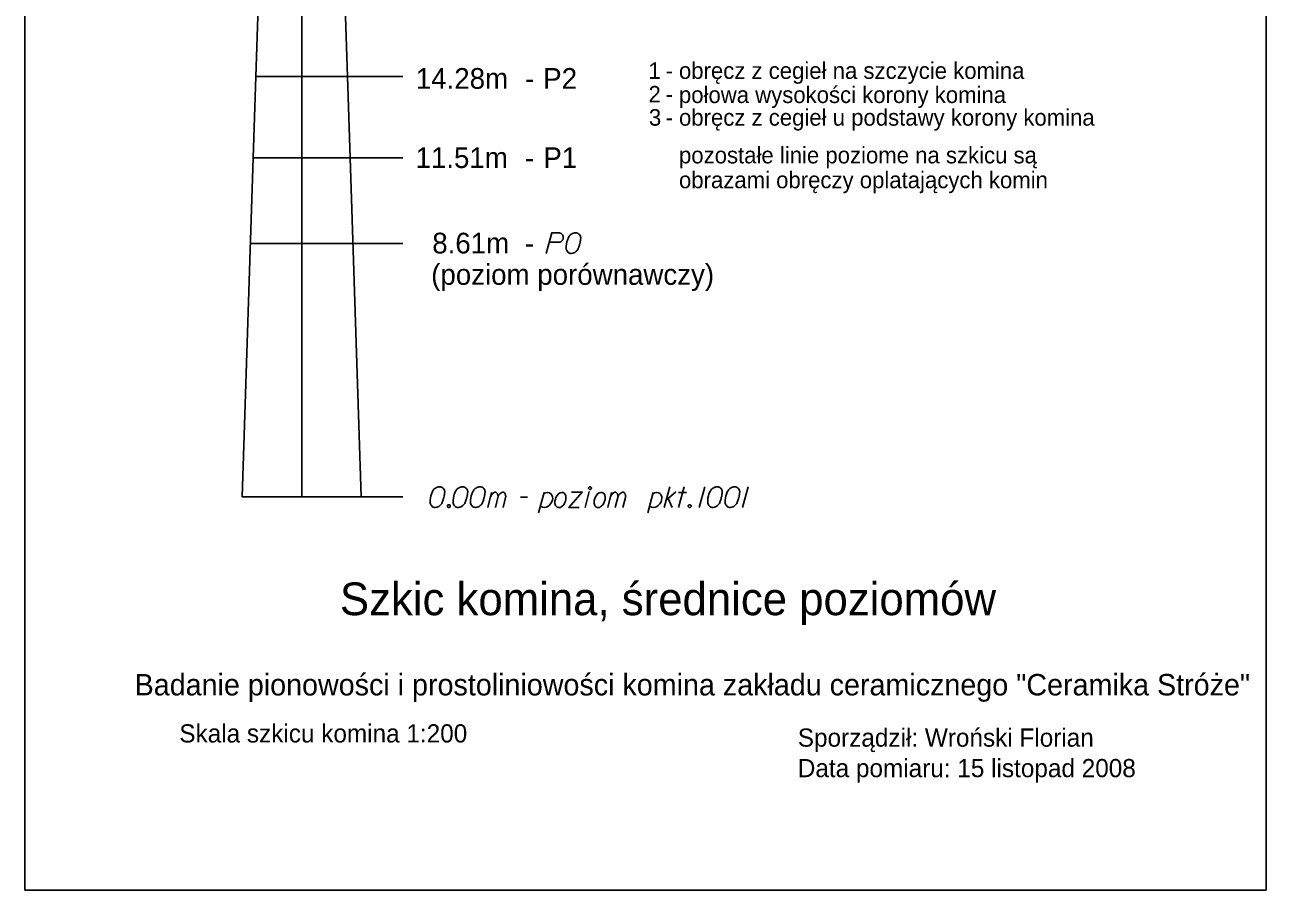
# Model space of a CAD drawing. Extents: x 138 to 6653, y -177 to 1520.
# Drawn here: x 316.78 to 337.78, y -30.54 to -15.91 of the extents above; entities that cross this region are included whole.
import ezdxf

# ---------------------------------------------------------------- set-up
doc = ezdxf.new("R2010")
doc.units = 0
for name, color, linetype in [('Opisy', 7, 'Continuous'), ('Ramka do drukowania', 7, 'Continuous'), ('Standard', 7, 'Continuous')]:
    doc.layers.add(name, color=color, linetype=linetype)

msp = doc.modelspace()

# ---------------------------------------------------------------- linework, layer by layer
at = {"layer": 'Ramka do drukowania'}
for p, q in [((316.779, -30.544), (316.779, -0.844)), ((337.779, -30.544), (337.779, -0.844)), ((316.779, -30.544), (337.779, -30.544))]:
    msp.add_line(p, q, dxfattribs=at)
at = {"layer": 'Standard'}
for p, q in [((321.463, -23.89), (321.463, -3.806)), ((320.689, -16.784), (320.731, -15.416)), ((322.237, -16.784), (322.195, -15.416)), ((320.644, -18.159), (320.689, -16.784)), ((321.463, -16.784), (320.689, -16.784)), ((321.463, -16.784), (323.173, -16.784)), ((322.282, -18.159), (322.237, -16.784)), ((320.457, -23.89), (320.644, -18.159)), ((321.463, -18.159), (320.644, -18.159)), ((321.463, -18.159), (323.173, -18.159)), ((322.469, -23.89), (322.282, -18.159)), ((321.463, -19.605), (320.597, -19.605)), ((321.463, -19.605), (323.173, -19.605)), ((321.463, -23.89), (320.457, -23.89)), ((321.463, -23.89), (323.173, -23.89))]:
    msp.add_line(p, q, dxfattribs=at)
for points in [[(325.6, -19.774), (325.694, -19.424), (325.812, -19.424), (325.829, -19.427), (325.837, -19.43), (325.854, -19.438), (325.865, -19.446), (325.873, -19.457), (325.881, -19.471), (325.887, -19.49), (325.889, -19.507), (325.887, -19.521), (325.884, -19.532), (325.878, -19.543), (325.873, -19.551), (325.865, -19.562), (325.854, -19.57), (325.845, -19.576), (325.832, -19.581), (325.818, -19.584), (325.652, -19.584)], [(326.102, -19.424), (326.096, -19.424), (326.08, -19.427), (326.069, -19.43), (326.06, -19.433), (326.047, -19.438), (326.03, -19.446), (326.016, -19.455), (326.002, -19.466), (325.994, -19.477), (325.986, -19.49), (325.978, -19.504), (325.969, -19.521), (325.964, -19.532), (325.958, -19.548), (325.95, -19.576), (325.942, -19.617), (325.936, -19.65), (325.936, -19.681), (325.939, -19.703), (325.95, -19.727), (325.958, -19.741), (325.972, -19.758), (325.989, -19.769), (325.997, -19.772), (326.013, -19.774), (326.027, -19.774), (326.049, -19.772), (326.069, -19.766), (326.082, -19.758), (326.102, -19.744), (326.11, -19.736), (326.121, -19.725), (326.129, -19.714), (326.135, -19.705), (326.14, -19.692), (326.143, -19.686), (326.149, -19.672), (326.154, -19.656), (326.16, -19.639), (326.162, -19.628), (326.165, -19.62), (326.168, -19.609), (326.173, -19.584), (326.176, -19.57), (326.179, -19.557), (326.182, -19.537), (326.184, -19.513), (326.184, -19.504), (326.182, -19.493), (326.179, -19.482), (326.171, -19.466), (326.162, -19.455), (326.154, -19.446), (326.143, -19.438), (326.132, -19.433), (326.124, -19.43), (326.115, -19.427), (326.102, -19.424)], [(323.8, -23.721), (323.794, -23.721), (323.778, -23.724), (323.767, -23.726), (323.759, -23.729), (323.745, -23.735), (323.728, -23.743), (323.714, -23.751), (323.701, -23.762), (323.692, -23.773), (323.684, -23.787), (323.676, -23.801), (323.668, -23.817), (323.662, -23.828), (323.657, -23.845), (323.648, -23.872), (323.64, -23.914), (323.635, -23.947), (323.635, -23.977), (323.637, -23.999), (323.648, -24.024), (323.657, -24.038), (323.67, -24.054), (323.687, -24.065), (323.695, -24.068), (323.712, -24.071), (323.725, -24.071), (323.748, -24.068), (323.767, -24.062), (323.781, -24.054), (323.8, -24.04), (323.808, -24.032), (323.819, -24.021), (323.827, -24.01), (323.833, -24.002), (323.838, -23.988), (323.841, -23.983), (323.847, -23.969), (323.852, -23.952), (323.858, -23.936), (323.861, -23.925), (323.863, -23.916), (323.866, -23.905), (323.872, -23.881), (323.874, -23.867), (323.877, -23.853), (323.88, -23.834), (323.883, -23.809), (323.883, -23.801), (323.88, -23.79), (323.877, -23.779), (323.869, -23.762), (323.861, -23.751), (323.852, -23.743), (323.841, -23.735), (323.83, -23.729), (323.822, -23.726), (323.814, -23.724), (323.8, -23.721)], [(324.188, -23.721), (324.183, -23.721), (324.166, -23.724), (324.155, -23.726), (324.147, -23.729), (324.133, -23.735), (324.117, -23.743), (324.103, -23.751), (324.089, -23.762), (324.081, -23.773), (324.073, -23.787), (324.064, -23.801), (324.056, -23.817), (324.051, -23.828), (324.045, -23.845), (324.037, -23.872), (324.029, -23.914), (324.023, -23.947), (324.023, -23.977), (324.026, -23.999), (324.037, -24.024), (324.045, -24.038), (324.059, -24.054), (324.075, -24.065), (324.084, -24.068), (324.1, -24.071), (324.114, -24.071), (324.136, -24.068), (324.155, -24.062), (324.169, -24.054), (324.188, -24.04), (324.197, -24.032), (324.208, -24.021), (324.216, -24.01), (324.221, -24.002), (324.227, -23.988), (324.23, -23.983), (324.235, -23.969), (324.241, -23.952), (324.246, -23.936), (324.249, -23.925), (324.252, -23.916), (324.255, -23.905), (324.26, -23.881), (324.263, -23.867), (324.266, -23.853), (324.268, -23.834), (324.271, -23.809), (324.271, -23.801), (324.268, -23.79), (324.266, -23.779), (324.257, -23.762), (324.249, -23.751), (324.241, -23.743), (324.23, -23.735), (324.219, -23.729), (324.21, -23.726), (324.202, -23.724), (324.188, -23.721)], [(324.483, -23.721), (324.478, -23.721), (324.461, -23.724), (324.45, -23.726), (324.442, -23.729), (324.428, -23.735), (324.412, -23.743), (324.398, -23.751), (324.384, -23.762), (324.376, -23.773), (324.368, -23.787), (324.359, -23.801), (324.351, -23.817), (324.345, -23.828), (324.34, -23.845), (324.332, -23.872), (324.323, -23.914), (324.318, -23.947), (324.318, -23.977), (324.321, -23.999), (324.332, -24.024), (324.34, -24.038), (324.354, -24.054), (324.37, -24.065), (324.379, -24.068), (324.395, -24.071), (324.409, -24.071), (324.431, -24.068), (324.45, -24.062), (324.464, -24.054), (324.483, -24.04), (324.492, -24.032), (324.503, -24.021), (324.511, -24.01), (324.516, -24.002), (324.522, -23.988), (324.525, -23.983), (324.53, -23.969), (324.536, -23.952), (324.541, -23.936), (324.544, -23.925), (324.547, -23.916), (324.549, -23.905), (324.555, -23.881), (324.558, -23.867), (324.56, -23.853), (324.563, -23.834), (324.566, -23.809), (324.566, -23.801), (324.563, -23.79), (324.56, -23.779), (324.552, -23.762), (324.544, -23.751), (324.536, -23.743), (324.525, -23.735), (324.514, -23.729), (324.505, -23.726), (324.497, -23.724), (324.483, -23.721)], [(326.333, -23.721), (326.346, -23.721), (326.355, -23.726), (326.363, -23.737), (326.363, -23.751), (326.355, -23.762), (326.346, -23.768), (326.333, -23.768), (326.324, -23.762), (326.316, -23.751), (326.316, -23.737), (326.324, -23.726), (326.333, -23.721)], [(327.595, -24.071), (327.689, -23.721)], [(327.84, -24.071), (327.931, -23.721)], [(328.284, -23.721), (328.19, -24.071)], [(328.496, -23.721), (328.49, -23.721), (328.474, -23.724), (328.463, -23.726), (328.455, -23.729), (328.441, -23.735), (328.424, -23.743), (328.411, -23.751), (328.397, -23.762), (328.388, -23.773), (328.38, -23.787), (328.372, -23.801), (328.364, -23.817), (328.358, -23.828), (328.353, -23.845), (328.344, -23.872), (328.336, -23.914), (328.331, -23.947), (328.331, -23.977), (328.333, -23.999), (328.344, -24.024), (328.353, -24.038), (328.366, -24.054), (328.383, -24.065), (328.391, -24.068), (328.408, -24.071), (328.422, -24.071), (328.444, -24.068), (328.463, -24.062), (328.477, -24.054), (328.496, -24.04), (328.504, -24.032), (328.515, -24.021), (328.523, -24.01), (328.529, -24.002), (328.535, -23.988), (328.537, -23.983), (328.543, -23.969), (328.548, -23.952), (328.554, -23.936), (328.557, -23.925), (328.559, -23.916), (328.562, -23.905), (328.568, -23.881), (328.57, -23.867), (328.573, -23.853), (328.576, -23.834), (328.579, -23.809), (328.579, -23.801), (328.576, -23.79), (328.573, -23.779), (328.565, -23.762), (328.557, -23.751), (328.548, -23.743), (328.537, -23.735), (328.526, -23.729), (328.518, -23.726), (328.51, -23.724), (328.496, -23.721)], [(328.791, -23.721), (328.785, -23.721), (328.769, -23.724), (328.758, -23.726), (328.749, -23.729), (328.736, -23.735), (328.719, -23.743), (328.705, -23.751), (328.692, -23.762), (328.683, -23.773), (328.675, -23.787), (328.667, -23.801), (328.658, -23.817), (328.653, -23.828), (328.647, -23.845), (328.639, -23.872), (328.631, -23.914), (328.625, -23.947), (328.625, -23.977), (328.628, -23.999), (328.639, -24.024), (328.647, -24.038), (328.661, -24.054), (328.678, -24.065), (328.686, -24.068), (328.703, -24.071), (328.716, -24.071), (328.738, -24.068), (328.758, -24.062), (328.772, -24.054), (328.791, -24.04), (328.799, -24.032), (328.81, -24.021), (328.818, -24.01), (328.824, -24.002), (328.829, -23.988), (328.832, -23.983), (328.838, -23.969), (328.843, -23.952), (328.849, -23.936), (328.851, -23.925), (328.854, -23.916), (328.857, -23.905), (328.862, -23.881), (328.865, -23.867), (328.868, -23.853), (328.871, -23.834), (328.873, -23.809), (328.873, -23.801), (328.871, -23.79), (328.868, -23.779), (328.86, -23.762), (328.851, -23.751), (328.843, -23.743), (328.832, -23.735), (328.821, -23.729), (328.813, -23.726), (328.805, -23.724), (328.791, -23.721)], [(329.014, -23.721), (328.92, -24.071)], [(324.613, -24.071), (324.676, -23.82)], [(324.66, -23.886), (324.673, -23.856), (324.687, -23.839), (324.704, -23.828), (324.72, -23.82), (324.731, -23.814), (324.748, -23.814), (324.753, -23.817), (324.764, -23.828), (324.775, -23.842), (324.784, -23.867), (324.786, -23.881), (324.8, -23.856), (324.817, -23.839), (324.833, -23.828), (324.85, -23.82), (324.864, -23.814), (324.877, -23.814), (324.888, -23.817), (324.897, -23.828), (324.905, -23.842), (324.913, -23.867), (324.916, -23.881), (324.869, -24.071)], [(324.74, -24.071), (324.786, -23.881)], [(325.164, -23.894), (325.283, -23.894)], [(325.47, -24.162), (325.564, -23.817)], [(325.556, -23.847), (325.583, -23.825), (325.624, -23.817), (325.658, -23.823), (325.68, -23.839), (325.696, -23.861), (325.707, -23.892), (325.71, -23.919), (325.704, -23.944), (325.696, -23.974), (325.674, -24.007), (325.647, -24.038), (325.605, -24.065), (325.569, -24.071), (325.536, -24.068), (325.5, -24.049)], [(325.864, -23.817), (325.884, -23.817), (325.906, -23.828), (325.928, -23.859), (325.93, -23.872), (325.933, -23.886), (325.933, -23.897), (325.933, -23.938), (325.925, -23.966), (325.911, -23.999), (325.895, -24.027), (325.867, -24.051), (325.842, -24.071), (325.801, -24.071), (325.784, -24.065), (325.768, -24.051), (325.759, -24.038), (325.748, -24.005), (325.748, -23.955), (325.754, -23.938), (325.765, -23.903), (325.776, -23.883), (325.782, -23.872), (325.809, -23.842), (325.837, -23.825), (325.864, -23.817)], [(326.03, -23.812), (326.209, -23.812), (325.98, -24.071), (326.156, -24.071)], [(326.256, -24.071), (326.327, -23.803)], [(326.526, -23.817), (326.545, -23.817), (326.567, -23.828), (326.589, -23.859), (326.592, -23.872), (326.595, -23.886), (326.595, -23.897), (326.595, -23.938), (326.586, -23.966), (326.572, -23.999), (326.556, -24.027), (326.528, -24.051), (326.504, -24.071), (326.462, -24.071), (326.446, -24.065), (326.429, -24.051), (326.421, -24.038), (326.41, -24.005), (326.41, -23.955), (326.415, -23.938), (326.426, -23.903), (326.437, -23.883), (326.443, -23.872), (326.47, -23.842), (326.498, -23.825), (326.526, -23.817)], [(326.641, -24.071), (326.705, -23.82)], [(326.688, -23.886), (326.702, -23.856), (326.716, -23.839), (326.732, -23.828), (326.749, -23.82), (326.76, -23.814), (326.776, -23.814), (326.782, -23.817), (326.793, -23.828), (326.804, -23.842), (326.812, -23.867), (326.815, -23.881), (326.829, -23.856), (326.845, -23.839), (326.862, -23.828), (326.878, -23.82), (326.892, -23.814), (326.906, -23.814), (326.917, -23.817), (326.925, -23.828), (326.933, -23.842), (326.942, -23.867), (326.944, -23.881), (326.898, -24.071)], [(326.768, -24.071), (326.815, -23.881)], [(327.317, -24.162), (327.41, -23.817)], [(327.402, -23.847), (327.43, -23.825), (327.471, -23.817), (327.504, -23.823), (327.526, -23.839), (327.543, -23.861), (327.554, -23.892), (327.556, -23.919), (327.551, -23.944), (327.543, -23.974), (327.52, -24.007), (327.493, -24.038), (327.452, -24.065), (327.416, -24.071), (327.383, -24.068), (327.347, -24.049)], [(327.628, -23.947), (327.793, -23.809)], [(327.661, -23.919), (327.733, -24.071)], [(327.84, -23.817), (327.972, -23.817)], [(323.946, -24.024), (323.96, -24.024), (323.968, -24.029), (323.976, -24.04), (323.976, -24.054), (323.968, -24.065), (323.96, -24.071), (323.946, -24.071), (323.938, -24.065), (323.929, -24.054), (323.929, -24.04), (323.938, -24.029), (323.946, -24.024)], [(328.019, -24.024), (328.033, -24.024), (328.041, -24.029), (328.05, -24.04), (328.05, -24.054), (328.041, -24.065), (328.033, -24.071), (328.019, -24.071), (328.011, -24.065), (328.003, -24.054), (328.003, -24.04), (328.011, -24.029), (328.019, -24.024)]]:
    msp.add_lwpolyline(points, dxfattribs=at)

# ---------------------------------------------------------------- texts
at = {"layer": 'Opisy'}
for s, p in [('Sporządził: Wroński Florian', (329.856, -28.117)), ('Data pomiaru: 15 listopad 2008', (329.856, -28.633))]:
    msp.add_text(s, height=0.30766, dxfattribs=at).set_placement(p)
at = {"layer": 'Standard'}
for s, height, p in [('1', 0.28, (327.327, -16.822)), ('obręcz z cegieł na szczycie komina', 0.27991, (327.845, -16.822)), ('14.28m', 0.35, (323.394, -16.989)), ('P2', 0.35, (325.549, -16.989)), ('-', 0.28, (327.618, -16.822)), ('-', 0.35, (325.24, -16.989)), ('2', 0.28, (327.33, -17.221)), ('połowa wysokości korony komina', 0.27991, (327.845, -17.23)), ('-', 0.28, (327.619, -17.221)), ('3', 0.28, (327.337, -17.613)), ('obręcz z cegieł u podstawy korony komina', 0.27991, (327.846, -17.613)), ('-', 0.28, (327.62, -17.613)), ('11.51m', 0.35, (323.389, -18.329)), ('P1', 0.35, (325.551, -18.329)), ('pozostałe linie poziome na szkicu są', 0.27991, (327.846, -18.251)), ('-', 0.35, (325.239, -18.329)), ('obrazami obręczy oplatających komin', 0.27991, (327.846, -18.671)), ('8.61m', 0.35, (323.672, -19.774)), ('-', 0.35, (325.239, -19.774)), ('(poziom porównawczy)', 0.35, (323.654, -20.305)), ('Szkic komina, średnice poziomów', 0.55314, (322.11, -25.893)), ('Badanie pionowości i prostoliniowości komina zakładu ceramicznego "Ceramika Stróże"', 0.36281, (318.637, -27.25)), ('Skala szkicu komina 1:200', 0.30766, (319.393, -28.046))]:
    msp.add_text(s, height=height, dxfattribs=at).set_placement(p)

doc.saveas('drawing.dxf')
